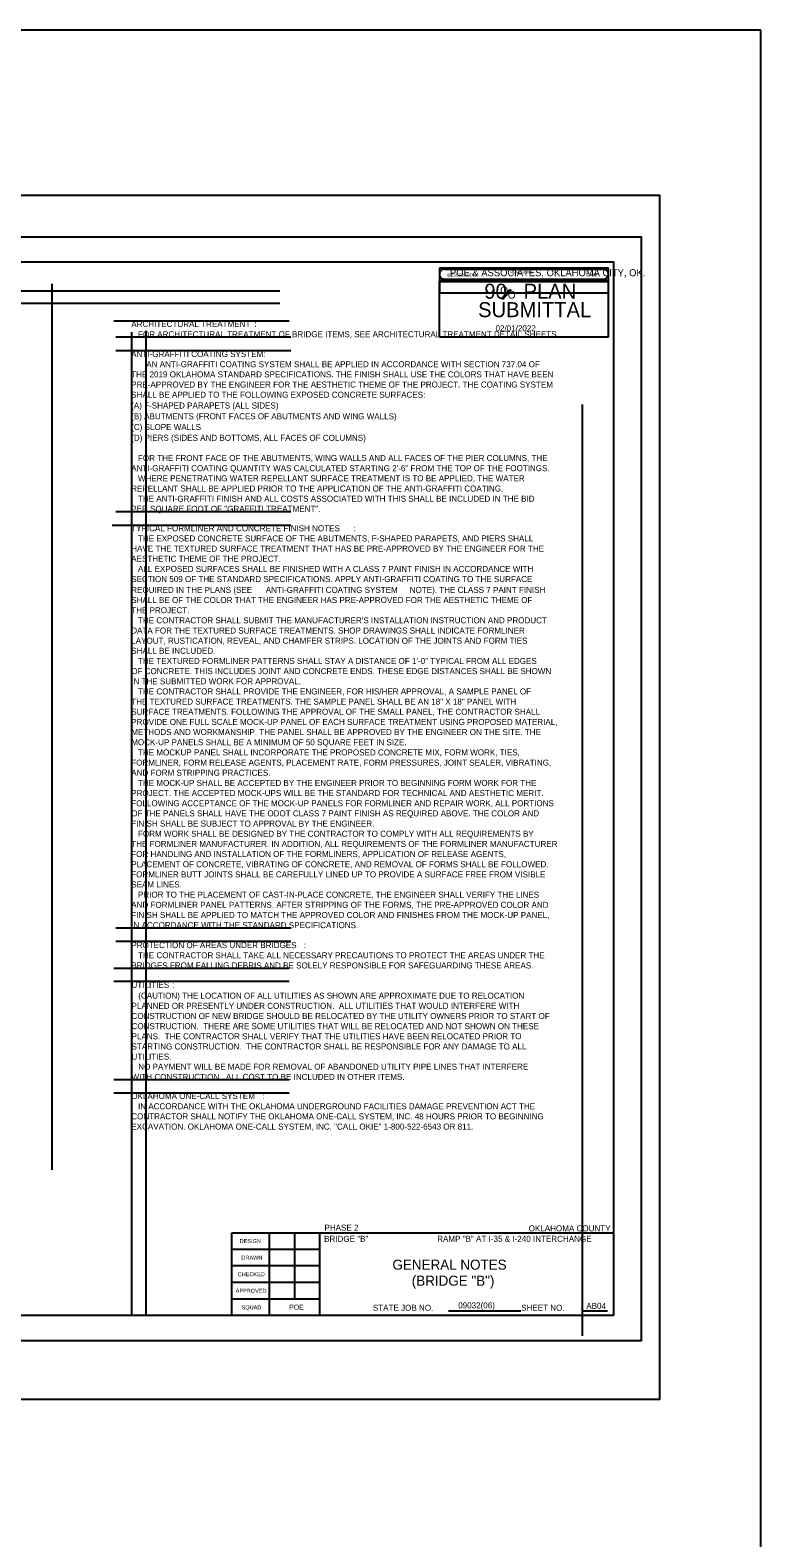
# Model space of a CAD drawing. Extents: x 12310.9 to 12354.4, y 579 to 640.5.
# Drawn here: x 12339.83 to 12354.38, y 610.44 to 640.49 of the extents above; entities that cross this region are included whole.
import ezdxf

# ---------------------------------------------------------------- set-up
doc = ezdxf.new("R2010")
doc.units = 0
for name, color, linetype in [('S', 7, 'Continuous'), ('SHT_Plot_Shape_Full', 7, 'Continuous'), ('SHT_Plot_Shape_Half', 7, 'Continuous'), ('SHT_Sheet_Border', 7, 'Continuous'), ('SHT_Stamp_90_Submit', 7, 'Continuous'), ('SHT_Stamp_Rev_Block', 7, 'Continuous'), ('SHT_Standard_Sheet_Lines', 7, 'Continuous'), ('SHT_Standard_Sheet_Txt', 7, 'Continuous'), ('T', 7, 'Continuous'), ('T-Title', 7, 'Continuous')]:
    doc.layers.add(name, color=color, linetype=linetype)

msp = doc.modelspace()

# ---------------------------------------------------------------- linework, layer by layer
at = {"layer": 'Defpoints'}
for p, q in [((12319.948, 635.295), (12344.799, 635.295)), ((12340.263, 635.43), (12340.263, 617.774)), ((12319.948, 635.045), (12344.799, 635.045)), ((12344.984, 634.692), (12341.495, 634.692)), ((12345.021, 634.368), (12341.532, 634.368)), ((12341.85, 634.47), (12341.85, 614.872)), ((12342.134, 634.498), (12342.134, 614.872)), ((12345.021, 634.099), (12341.532, 634.099)), ((12341.85, 633.284), (12341.85, 614.872)), ((12350.821, 633.03), (12350.821, 614.468)), ((12345.023, 630.889), (12341.533, 630.889)), ((12344.953, 630.619), (12341.464, 630.619)), ((12345.023, 630.619), (12341.533, 630.619)), ((12345.023, 622.593), (12341.533, 622.593)), ((12345.023, 622.324), (12341.533, 622.324)), ((12344.984, 621.79), (12341.495, 621.79)), ((12344.984, 621.528), (12341.495, 621.528)), ((12344.984, 619.569), (12341.495, 619.569)), ((12344.984, 619.307), (12341.495, 619.307))]:
    msp.add_line(p, q, dxfattribs=at)
at = {"layer": 'S'}
msp.add_lwpolyline([(12354.38, 640.488), (12310.944, 640.488), (12310.944, 579.031), (12354.38, 579.031)], close=True, dxfattribs=at)
at = {"layer": 'SHT_Plot_Shape_Full'}
msp.add_lwpolyline([(12316.36, 637.197), (12352.36, 637.197), (12352.36, 613.197), (12316.36, 613.197)], close=True, dxfattribs=at)
at = {"layer": 'SHT_Plot_Shape_Half'}
msp.add_lwpolyline([(12317.998, 636.372), (12351.998, 636.372), (12351.998, 614.372), (12317.998, 614.372)], close=True, dxfattribs=at)
at = {"layer": 'SHT_Sheet_Border'}
for p, q in [((12343.848, 614.872), (12343.848, 616.522)), ((12343.848, 616.522), (12351.448, 616.522)), ((12345.598, 614.872), (12345.598, 616.523))]:
    msp.add_line(p, q, dxfattribs=at)
msp.add_lwpolyline([(12351.448, 614.872), (12319.948, 614.872), (12319.948, 635.872), (12351.448, 635.872)], close=True, dxfattribs=at)
at = {"layer": 'SHT_Stamp_90_Submit'}
for p, q in [((12347.979, 635.477), (12351.345, 635.477)), ((12347.979, 634.378), (12347.979, 635.477)), ((12348.079, 635.727), (12351.245, 635.727)), ((12348.079, 635.527), (12351.245, 635.527)), ((12351.345, 634.378), (12351.345, 635.477)), ((12349.222, 635.139), (12349.377, 635.311)), ((12349.24, 635.139), (12349.395, 635.311)), ((12349.245, 635.139), (12349.4, 635.311)), ((12349.252, 635.139), (12349.408, 635.311)), ((12349.377, 635.311), (12349.408, 635.311)), ((12349.222, 635.139), (12349.252, 635.139)), ((12347.979, 634.378), (12351.345, 634.378))]:
    msp.add_line(p, q, dxfattribs=at)
for centre, start, end in [((12348.079, 635.627), 89.9952, 270), ((12351.245, 635.627), 270, 90.0048)]:
    msp.add_arc(centre, 0.1, start, end, dxfattribs=at)
at = {"layer": 'SHT_Stamp_Rev_Block'}
for p, q in [((12347.979, 635.748), (12347.979, 635.248)), ((12351.345, 635.748), (12347.979, 635.748)), ((12351.345, 635.248), (12351.345, 635.748)), ((12351.345, 635.498), (12347.979, 635.498)), ((12351.345, 635.248), (12347.979, 635.248))]:
    msp.add_line(p, q, dxfattribs=at)
at = {"layer": 'SHT_Standard_Sheet_Lines'}
for p, q in [((12344.598, 614.872), (12344.598, 616.523)), ((12345.098, 615.202), (12345.098, 616.523)), ((12348.159, 614.968), (12349.599, 614.968)), ((12350.823, 614.968), (12351.326, 614.968))]:
    msp.add_line(p, q, dxfattribs=at)
for points in [[(12345.598, 616.192), (12343.848, 616.192)], [(12345.598, 615.862), (12343.848, 615.862)], [(12345.598, 615.532), (12343.848, 615.532)], [(12345.598, 615.202), (12343.848, 615.202)]]:
    msp.add_lwpolyline(points, dxfattribs=at)

# ---------------------------------------------------------------- texts
at = {"layer": 'SHT_Stamp_90_Submit'}
for s, height, p in [('POE & ASSOCIATES, OKLAHOMA CITY, OK.', 0.14, (12348.189, 635.584)), ('90   PLAN', 0.3, (12348.874, 635.135)), ('O', 0.153, (12349.187, 635.224)), ('O', 0.153, (12349.339, 635.139)), ('SUBMITTAL', 0.3, (12348.75, 634.768)), ('02/01/2022', 0.12, (12349.096, 634.487))]:
    msp.add_text(s, height=height, rotation=360, dxfattribs=at).set_placement(p)
at = {"layer": 'SHT_Stamp_Rev_Block'}
for s, p in [('DESCRIPTION', (12348.139, 635.576)), ('REVISIONS', (12349.388, 635.635)), ('DATE', (12350.908, 635.58))]:
    msp.add_text(s, height=0.06, dxfattribs=at).set_placement(p)
at = {"layer": 'SHT_Standard_Sheet_Txt'}
for s, height, p in [('DESIGN', 0.08, (12344, 616.317)), ('DRAWN', 0.08, (12344.035, 615.987)), ('CHECKED', 0.08, (12343.961, 615.656)), ('APPROVED', 0.08, (12343.922, 615.326)), ('SQUAD', 0.08, (12344.039, 614.996)), ('STATE JOB NO.', 0.12, (12346.654, 614.968)), ('SHEET NO. ', 0.12, (12349.607, 614.968))]:
    msp.add_text(s, height=height, dxfattribs=at).set_placement(p)
at = {"layer": 'T'}
for s, height, p in [('ARCHITECTURAL TREATMENT', 0.12, (12341.843, 634.572)), (':', 0.12, (12344.295, 634.572)), ('   FOR ARCHITECTURAL TREATMENT OF BRIDGE ITEMS, SEE ARCHITECTURAL TREATMENT DETAIL SHEETS.', 0.12, (12341.843, 634.369)), ('ANTI-GRAFFITI COATING SYSTEM:', 0.12, (12341.841, 633.973)), ('THE 2019 OKLAHOMA STANDARD SPECIFICATIONS. THE FINISH SHALL USE THE COLORS THAT HAVE BEEN ', 0.12, (12341.841, 633.568)), ('AN ANTI-GRAFFITI COATING SYSTEM SHALL BE APPLIED IN ACCORDANCE WITH SECTION 737.04 OF ', 0.12, (12342.141, 633.771)), ('PRE-APPROVED BY THE ENGINEER FOR THE AESTHETIC THEME OF THE PROJECT. THE COATING SYSTEM ', 0.12, (12341.841, 633.366)), ('SHALL BE APPLIED TO THE FOLLOWING EXPOSED CONCRETE SURFACES:', 0.12, (12341.841, 633.163)), ('(A) F-SHAPED PARAPETS (ALL SIDES)', 0.12, (12341.841, 632.948)), ('(B) ABUTMENTS (FRONT FACES OF ABUTMENTS AND WING WALLS)', 0.12, (12341.841, 632.734)), ('(C) SLOPE WALLS', 0.12, (12341.841, 632.519)), ('(D) PIERS (SIDES AND BOTTOMS, ALL FACES OF COLUMNS)', 0.12, (12341.841, 632.304)), ('   FOR THE FRONT FACE OF THE ABUTMENTS, WING WALLS AND ALL FACES OF THE PIER COLUMNS, THE ', 0.12, (12341.841, 631.902)), ('ANTI-GRAFFITI COATING QUANTITY WAS CALCULATED STARTING 2\'-6" FROM THE TOP OF THE FOOTINGS.', 0.12, (12341.841, 631.699)), ('   WHERE PENETRATING WATER REPELLANT SURFACE TREATMENT IS TO BE APPLIED, THE WATER ', 0.12, (12341.841, 631.497)), ('REPELLANT SHALL BE APPLIED PRIOR TO THE APPLICATION OF THE ANTI-GRAFFITI COATING.', 0.12, (12341.841, 631.294)), ('PER SQUARE FOOT OF "GRAFFITI TREATMENT".', 0.12, (12341.841, 630.889)), ('   THE ANTI-GRAFFITI FINISH AND ALL COSTS ASSOCIATED WITH THIS SHALL BE INCLUDED IN THE BID ', 0.12, (12341.841, 631.091)), ('TYPICAL FORMLINER AND CONCRETE FINISH NOTES', 0.12, (12341.842, 630.502)), ('   THE EXPOSED CONCRETE SURFACE OF THE ABUTMENTS, F-SHAPED PARAPETS, AND PIERS SHALL ', 0.12, (12341.842, 630.299)), (':', 0.12, (12346.26, 630.502)), ('HAVE THE TEXTURED SURFACE TREATMENT THAT HAS BE PRE-APPROVED BY THE ENGINEER FOR THE ', 0.12, (12341.842, 630.097)), ('AESTHETIC THEME OF THE PROJECT.', 0.12, (12341.842, 629.894)), ('   ALL EXPOSED SURFACES SHALL BE FINISHED WITH A CLASS 7 PAINT FINISH IN ACCORDANCE WITH ', 0.12, (12341.842, 629.692)), ('SECTION 509 OF THE STANDARD SPECIFICATIONS. APPLY ANTI-GRAFFITI COATING TO THE SURFACE ', 0.12, (12341.842, 629.489)), ('SHALL BE OF THE COLOR THAT THE ENGINEER HAS PRE-APPROVED FOR THE AESTHETIC THEME OF ', 0.12, (12341.842, 629.072)), ('REQUIRED IN THE PLANS (SEE ', 0.12, (12341.842, 629.274)), ('ANTI-GRAFFITI COATING SYSTEM', 0.12, (12344.519, 629.274)), (' NOTE). THE CLASS 7 PAINT FINISH ', 0.12, (12347.343, 629.274)), ('THE PROJECT.', 0.12, (12341.842, 628.869)), ('DATA FOR THE TEXTURED SURFACE TREATMENTS. SHOP DRAWINGS SHALL INDICATE FORMLINER ', 0.12, (12341.842, 628.464)), ("   THE CONTRACTOR SHALL SUBMIT THE MANUFACTURER'S INSTALLATION INSTRUCTION AND PRODUCT ", 0.12, (12341.842, 628.667)), ('LAYOUT, RUSTICATION, REVEAL, AND CHAMFER STRIPS. LOCATION OF THE JOINTS AND FORM TIES ', 0.12, (12341.842, 628.261)), ('SHALL BE INCLUDED.', 0.12, (12341.842, 628.06)), ('   THE TEXTURED FORMLINER PATTERNS SHALL STAY A DISTANCE OF 1\'-0" TYPICAL FROM ALL EDGES ', 0.12, (12341.842, 627.858)), ('OF CONCRETE. THIS INCLUDES JOINT AND CONCRETE ENDS. THESE EDGE DISTANCES SHALL BE SHOWN ', 0.12, (12341.842, 627.655)), ('IN THE SUBMITTED WORK FOR APPROVAL.', 0.12, (12341.842, 627.453)), ('   THE CONTRACTOR SHALL PROVIDE THE ENGINEER, FOR HIS/HER APPROVAL, A SAMPLE PANEL OF ', 0.12, (12341.842, 627.25)), ('THE TEXTURED SURFACE TREATMENTS. THE SAMPLE PANEL SHALL BE AN 18" X 18" PANEL WITH ', 0.12, (12341.842, 627.048)), ('SURFACE TREATMENTS. FOLLOWING THE APPROVAL OF THE SMALL PANEL, THE CONTRACTOR SHALL ', 0.12, (12341.842, 626.845)), ('PROVIDE ONE FULL SCALE MOCK-UP PANEL OF EACH SURFACE TREATMENT USING PROPOSED MATERIAL, ', 0.12, (12341.842, 626.643)), ('METHODS AND WORKMANSHIP. THE PANEL SHALL BE APPROVED BY THE ENGINEER ON THE SITE. THE ', 0.12, (12341.842, 626.44)), ('MOCK-UP PANELS SHALL BE A MINIMUM OF 50 SQUARE FEET IN SIZE.', 0.12, (12341.842, 626.238)), ('   THE MOCKUP PANEL SHALL INCORPORATE THE PROPOSED CONCRETE MIX, FORM WORK, TIES, ', 0.12, (12341.842, 626.035)), ('FORMLINER, FORM RELEASE AGENTS, PLACEMENT RATE, FORM PRESSURES, JOINT SEALER, VIBRATING, ', 0.12, (12341.842, 625.832)), ('AND FORM STRIPPING PRACTICES.', 0.12, (12341.842, 625.63)), ('   THE MOCK-UP SHALL BE ACCEPTED BY THE ENGINEER PRIOR TO BEGINNING FORM WORK FOR THE ', 0.12, (12341.842, 625.427)), ('PROJECT. THE ACCEPTED MOCK-UPS WILL BE THE STANDARD FOR TECHNICAL AND AESTHETIC MERIT. ', 0.12, (12341.842, 625.225)), ('OF THE PANELS SHALL HAVE THE ODOT CLASS 7 PAINT FINISH AS REQUIRED ABOVE. THE COLOR AND ', 0.12, (12341.842, 624.82)), ('FOLLOWING ACCEPTANCE OF THE MOCK-UP PANELS FOR FORMLINER AND REPAIR WORK, ALL PORTIONS ', 0.12, (12341.842, 625.022)), ('FINISH SHALL BE SUBJECT TO APPROVAL BY THE ENGINEER.', 0.12, (12341.842, 624.617)), ('THE FORMLINER MANUFACTURER. IN ADDITION, ALL REQUIREMENTS OF THE FORMLINER MANUFACTURER ', 0.12, (12341.842, 624.212)), ('   FORM WORK SHALL BE DESIGNED BY THE CONTRACTOR TO COMPLY WITH ALL REQUIREMENTS BY ', 0.12, (12341.842, 624.414)), ('FOR HANDLING AND INSTALLATION OF THE FORMLINERS, APPLICATION OF RELEASE AGENTS, ', 0.12, (12341.842, 624.009)), ('PLACEMENT OF CONCRETE, VIBRATING OF CONCRETE, AND REMOVAL OF FORMS SHALL BE FOLLOWED. ', 0.12, (12341.842, 623.807)), ('FORMLINER BUTT JOINTS SHALL BE CAREFULLY LINED UP TO PROVIDE A SURFACE FREE FROM VISIBLE ', 0.12, (12341.842, 623.604)), ('SEAM LINES.', 0.12, (12341.842, 623.404)), ('   PRIOR TO THE PLACEMENT OF CAST-IN-PLACE CONCRETE, THE ENGINEER SHALL VERIFY THE LINES ', 0.12, (12341.842, 623.201)), ('AND FORMLINER PANEL PATTERNS. AFTER STRIPPING OF THE FORMS, THE PRE-APPROVED COLOR AND ', 0.12, (12341.842, 622.998)), ('FINISH SHALL BE APPLIED TO MATCH THE APPROVED COLOR AND FINISHES FROM THE MOCK-UP PANEL, ', 0.12, (12341.842, 622.796)), ('IN ACCORDANCE WITH THE STANDARD SPECIFICATIONS.', 0.12, (12341.842, 622.593)), ('PROTECTION OF AREAS UNDER BRIDGES', 0.12, (12341.844, 622.195)), (':', 0.12, (12345.277, 622.195)), ('   THE CONTRACTOR SHALL TAKE ALL NECESSARY PRECAUTIONS TO PROTECT THE AREAS UNDER THE ', 0.12, (12341.844, 621.993)), ('BRIDGES FROM FALLING DEBRIS AND BE SOLELY RESPONSIBLE FOR SAFEGUARDING THESE AREAS.', 0.12, (12341.844, 621.79)), ('UTILITIES', 0.12, (12341.848, 621.403)), (':', 0.12, (12342.66, 621.403)), ('PLANNED OR PRESENTLY UNDER CONSTRUCTION.  ALL UTILITIES THAT WOULD INTERFERE WITH ', 0.12, (12341.848, 620.985)), ('   (CAUTION) THE LOCATION OF ALL UTILITIES AS SHOWN ARE APPROXIMATE DUE TO RELOCATION ', 0.12, (12341.848, 621.188)), ('CONSTRUCTION OF NEW BRIDGE SHOULD BE RELOCATED BY THE UTILITY OWNERS PRIOR TO START OF ', 0.12, (12341.848, 620.783)), ('CONSTRUCTION.  THERE ARE SOME UTILITIES THAT WILL BE RELOCATED AND NOT SHOWN ON THESE', 0.12, (12341.848, 620.58)), ('PLANS.  THE CONTRACTOR SHALL VERIFY THAT THE UTILITIES HAVE BEEN RELOCATED PRIOR TO ', 0.12, (12341.848, 620.378)), ('STARTING CONSTRUCTION.  THE CONTRACTOR SHALL BE RESPONSIBLE FOR ANY DAMAGE TO ALL ', 0.12, (12341.848, 620.175)), ('UTILITIES.', 0.12, (12341.848, 619.974)), ('   NO PAYMENT WILL BE MADE FOR REMOVAL OF ABANDONED UTILITY PIPE LINES THAT INTERFERE ', 0.12, (12341.848, 619.772)), ('WITH CONSTRUCTION.  ALL COST TO BE INCLUDED IN OTHER ITEMS. ', 0.12, (12341.848, 619.569)), ('OKLAHOMA ONE-CALL SYSTEM', 0.12, (12341.843, 619.187)), (':', 0.12, (12344.451, 619.187)), ('   IN ACCORDANCE WITH THE OKLAHOMA UNDERGROUND FACILITIES DAMAGE PREVENTION ACT THE ', 0.12, (12341.843, 618.984)), ('CONTRACTOR SHALL NOTIFY THE OKLAHOMA ONE-CALL SYSTEM, INC. 48 HOURS PRIOR TO BEGINNING ', 0.12, (12341.843, 618.782)), ('EXCAVATION. OKLAHOMA ONE-CALL SYSTEM, INC. "CALL OKIE" 1-800-522-6543 OR 811.', 0.12, (12341.843, 618.579)), ('PHASE 2', 0.12, (12345.69, 616.565)), ('OKLAHOMA COUNTY', 0.12, (12349.756, 616.55)), ('BRIDGE "B"', 0.12, (12345.683, 616.342)), ('RAMP "B" AT I-35 & I-240 INTERCHANGE', 0.12, (12347.935, 616.342)), ('POE', 0.1, (12344.987, 614.99)), ('09032(06)', 0.12, (12348.353, 615.016)), ('AB04', 0.12, (12350.904, 615.006))]:
    msp.add_text(s, height=height, dxfattribs=at).set_placement(p)
at = {"layer": 'T-Title'}
for s, p in [('GENERAL NOTES', (12347.044, 615.787)), ('(BRIDGE "B")', (12347.428, 615.468))]:
    msp.add_text(s, height=0.2, dxfattribs=at).set_placement(p)

doc.saveas('drawing.dxf')
